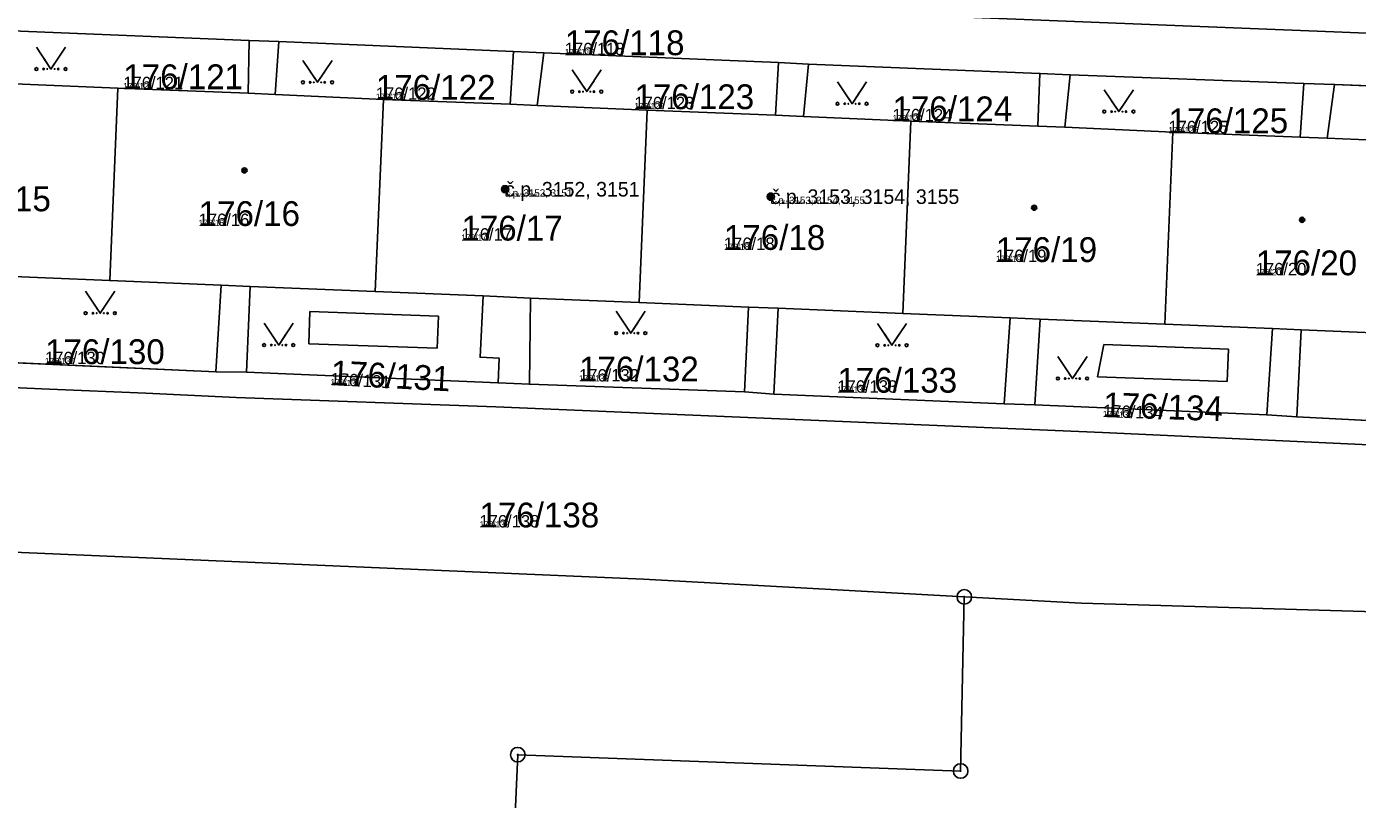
# Model space of a CAD drawing. Extents: x -759873 to -758487, y -975024 to -973516.
# Drawn here: x -759662.7 to -759571.4, y -974909.7 to -974856.7 of the extents above; entities that cross this region are included whole.
import ezdxf

# ---------------------------------------------------------------- set-up
doc = ezdxf.new("R2010")
doc.units = 0
for name, color, linetype in [('KAT_02_hranice parcel', 7, 'Continuous'), ('KAT_03_1000_st čísla parcelní', 7, 'Continuous'), ('KAT_03_1000_čísla parcelní', 7, 'Continuous'), ('KAT_03_1000_čísla popisná', 7, 'Continuous'), ('KAT_03_250_st čísla parcelní', 7, 'Continuous'), ('KAT_03_250_čísla parcelní', 7, 'Continuous'), ('KAT_03_250_čísla popisná', 7, 'Continuous'), ('KAT_03_500_st čísla parcelní', 7, 'Continuous'), ('KAT_03_500_čísla parcelní', 7, 'Continuous'), ('KAT_03_500_čísla popisná', 7, 'Continuous'), ('KAT_04_vnitřní kresba', 7, 'Continuous'), ('KAT_05_1000_značky kultur', 7, 'Continuous'), ('KAT_05_250_značky kultur', 7, 'Continuous'), ('KAT_05_500_značky kultur', 7, 'Continuous'), ('KAT_07_1000_značky budov', 7, 'Continuous'), ('KAT_07_250_značky budov', 7, 'Continuous'), ('KAT_07_500_značky budov', 7, 'Continuous'), ('KAT_11_značky bodu BP', 7, 'Continuous'), ('KAT_14_plocha_budovy', 7, 'Continuous'), ('KAT_14_plocha_pozemek', 7, 'Continuous')]:
    doc.layers.add(name, color=color, linetype=linetype)

msp = doc.modelspace()

# ---------------------------------------------------------------- linework, layer by layer
at = {"layer": 'KAT_02_hranice parcel'}
for p, q in [((-759663.64, -974857.01), (-759647.4, -974857.67)), ((-759645.37, -974857.74), (-759647.4, -974857.67)), ((-759645.37, -974857.74), (-759629.27, -974858.42)), ((-759627.19, -974858.51), (-759629.27, -974858.42)), ((-759627.19, -974858.51), (-759611.09, -974859.18)), ((-759609.03, -974859.28), (-759611.09, -974859.18)), ((-759609.03, -974859.28), (-759593.15, -974859.92)), ((-759591.08, -974860.01), (-759593.15, -974859.92)), ((-759591.08, -974860.01), (-759575.05, -974860.6)), ((-759572.94, -974860.67), (-759575.05, -974860.6)), ((-759656.96, -974874.12), (-759656.41, -974860.94)), ((-759572.94, -974860.67), (-759556.86, -974861.35)), ((-759638.74, -974874.88), (-759638.19, -974861.7)), ((-759620.64, -974875.63), (-759620.1, -974862.45)), ((-759602.55, -974876.37), (-759602.01, -974863.19)), ((-759584.58, -974877.12), (-759584.03, -974863.94)), ((-759665.96, -974879.65), (-759649.68, -974880.37)), ((-759649.68, -974880.37), (-759647.57, -974880.4)), ((-759647.57, -974880.4), (-759630.32, -974881.14)), ((-759630.32, -974881.14), (-759628.17, -974881.23)), ((-759628.17, -974881.23), (-759613.41, -974881.75)), ((-759613.41, -974881.75), (-759611.4, -974881.91)), ((-759611.4, -974881.91), (-759595.61, -974882.57)), ((-759595.61, -974882.57), (-759593.51, -974882.64)), ((-759593.51, -974882.64), (-759577.59, -974883.34)), ((-759577.59, -974883.34), (-759575.54, -974883.47)), ((-759575.54, -974883.47), (-759559.19, -974884.32))]:
    msp.add_line(p, q, dxfattribs=at)
for points in [[(-759558.86, -974857.64), (-759572.99, -974857.06), (-759590.79, -974856.36), (-759612.08, -974855.52)], [(-759656.41, -974860.94), (-759664.04, -974860.6), (-759663.64, -974857.01)], [(-759647.4, -974857.67), (-759647.46, -974861.28), (-759656.41, -974860.94)], [(-759638.19, -974861.7), (-759645.61, -974861.36), (-759645.37, -974857.74)], [(-759629.27, -974858.42), (-759629.5, -974862.03), (-759638.19, -974861.7)], [(-759620.1, -974862.45), (-759627.64, -974862.11), (-759627.19, -974858.51)], [(-759611.09, -974859.18), (-759611.29, -974862.79), (-759620.1, -974862.45)], [(-759602.01, -974863.19), (-759609.38, -974862.87), (-759609.03, -974859.28)], [(-759593.15, -974859.92), (-759593.3, -974863.54), (-759602.01, -974863.19)], [(-759584.03, -974863.94), (-759591.44, -974863.61), (-759591.08, -974860.01)], [(-759575.05, -974860.6), (-759575.29, -974864.28), (-759584.03, -974863.94)], [(-759565.93, -974864.69), (-759573.44, -974864.36), (-759572.94, -974860.67)], [(-759523.06, -974862.69), (-759523.84, -974879.95), (-759532.34, -974886.85), (-759531.93, -974887.1), (-759532.68, -974898.32), (-759561.57, -974897.09), (-759590.3, -974896.25), (-759598.34, -974895.81)], [(-759665.96, -974879.65), (-759665.8, -974873.76), (-759656.96, -974874.12)], [(-759656.96, -974874.12), (-759649.32, -974874.44), (-759649.68, -974880.37)], [(-759647.57, -974880.4), (-759647.32, -974874.52), (-759638.74, -974874.88)], [(-759638.74, -974874.88), (-759631.34, -974875.18), (-759631.56, -974879.38), (-759630.25, -974879.44), (-759630.32, -974881.14)], [(-759628.17, -974881.23), (-759628.1, -974875.32), (-759620.64, -974875.63)], [(-759620.64, -974875.63), (-759613.14, -974875.94), (-759613.41, -974881.75)], [(-759611.4, -974881.91), (-759611.1, -974876.02), (-759602.55, -974876.37)], [(-759602.55, -974876.37), (-759595.19, -974876.68), (-759595.61, -974882.57)], [(-759593.51, -974882.64), (-759593.14, -974876.76), (-759584.58, -974877.12)], [(-759584.58, -974877.12), (-759577.2, -974877.42), (-759577.59, -974883.34)], [(-759575.54, -974883.47), (-759575.23, -974877.51), (-759566.48, -974877.87)], [(-759704.55, -974885.39), (-759692.32, -974885.8), (-759692.32, -974891.5), (-759674.78, -974892.27), (-759648.58, -974893.39), (-759620.34, -974894.6), (-759598.34, -974895.81)], [(-759598.34, -974895.81), (-759598.59, -974907.75), (-759628.97, -974906.63), (-759630.26, -974935.59), (-759598.78, -974936.67), (-759598.41, -974971.14)]]:
    msp.add_lwpolyline(points, dxfattribs=at)
at = {"layer": 'KAT_03_1000_čísla popisná'}
for centre in [(-759629.84, -974867.86), (-759611.62, -974868.37)]:
    msp.add_circle(centre, 0.25, dxfattribs=at)
at = {"layer": 'KAT_03_250_čísla popisná'}
for centre in [(-759629.84, -974867.86), (-759611.62, -974868.37)]:
    msp.add_circle(centre, 0.0625, dxfattribs=at)
at = {"layer": 'KAT_03_500_čísla popisná'}
for centre in [(-759629.84, -974867.86), (-759611.62, -974868.37)]:
    msp.add_circle(centre, 0.125, dxfattribs=at)
at = {"layer": 'KAT_04_vnitřní kresba'}
for p, q in [((-759647.46, -974861.28), (-759645.61, -974861.36)), ((-759629.5, -974862.03), (-759627.64, -974862.11)), ((-759611.29, -974862.79), (-759609.38, -974862.87)), ((-759593.3, -974863.54), (-759591.44, -974863.61)), ((-759575.29, -974864.28), (-759573.44, -974864.36)), ((-759649.32, -974874.44), (-759647.32, -974874.52)), ((-759631.34, -974875.18), (-759628.1, -974875.32)), ((-759613.14, -974875.94), (-759611.1, -974876.02)), ((-759643.29, -974878.46), (-759643.23, -974876.24)), ((-759643.23, -974876.24), (-759634.41, -974876.56)), ((-759634.49, -974878.76), (-759634.41, -974876.56)), ((-759595.19, -974876.68), (-759593.14, -974876.76)), ((-759577.2, -974877.42), (-759575.23, -974877.51)), ((-759643.29, -974878.46), (-759634.49, -974878.76)), ((-759589.21, -974880.73), (-759588.77, -974878.51)), ((-759588.77, -974878.51), (-759580.22, -974878.83)), ((-759580.31, -974881.04), (-759580.22, -974878.83)), ((-759670.56, -974881.16), (-759661.09, -974881.56)), ((-759661.09, -974881.56), (-759654.48, -974881.84)), ((-759589.21, -974880.73), (-759580.31, -974881.04)), ((-759654.48, -974881.84), (-759648.28, -974882.15)), ((-759648.28, -974882.15), (-759630.47, -974882.79)), ((-759630.47, -974882.79), (-759588.86, -974884.55)), ((-759588.86, -974884.55), (-759570.57, -974885.39))]:
    msp.add_line(p, q, dxfattribs=at)
at = {"layer": 'KAT_05_1000_značky kultur'}
for points in [[(-759661.99, -974858.119), (-759660.99, -974859.62), (-759659.99, -974858.119)], [(-759643.71, -974859.029), (-759642.71, -974860.53), (-759641.71, -974859.029)], [(-759625.24, -974859.669), (-759624.24, -974861.17), (-759623.24, -974859.669)], [(-759607.04, -974860.499), (-759606.04, -974862), (-759605.04, -974860.499)], [(-759588.74, -974861.039), (-759587.74, -974862.54), (-759586.74, -974861.039)], [(-759658.61, -974874.859), (-759657.61, -974876.36), (-759656.61, -974874.859)], [(-759622.22, -974876.229), (-759621.22, -974877.73), (-759620.22, -974876.229)], [(-759646.37, -974877.049), (-759645.37, -974878.55), (-759644.37, -974877.049)], [(-759604.3, -974877.059), (-759603.3, -974878.56), (-759602.3, -974877.059)], [(-759591.92, -974879.339), (-759590.92, -974880.84), (-759589.92, -974879.339)]]:
    msp.add_lwpolyline(points, dxfattribs=at)
for centre in [(-759661.99, -974859.619), (-759659.99, -974859.619), (-759643.71, -974860.529), (-759641.71, -974860.529), (-759625.24, -974861.169), (-759623.24, -974861.169), (-759607.04, -974861.999), (-759605.04, -974861.999), (-759588.74, -974862.539), (-759586.74, -974862.539), (-759658.61, -974876.359), (-759656.61, -974876.359), (-759622.22, -974877.729), (-759620.22, -974877.729), (-759646.37, -974878.549), (-759644.37, -974878.549), (-759604.3, -974878.559), (-759602.3, -974878.559), (-759591.92, -974880.839), (-759589.92, -974880.839)]:
    msp.add_circle(centre, 0.1, dxfattribs=at)
at = {"layer": 'KAT_05_250_značky kultur'}
for points in [[(-759661.24, -974859.245), (-759660.99, -974859.62), (-759660.74, -974859.245)], [(-759642.96, -974860.155), (-759642.71, -974860.53), (-759642.46, -974860.155)], [(-759624.49, -974860.795), (-759624.24, -974861.17), (-759623.99, -974860.795)], [(-759606.29, -974861.625), (-759606.04, -974862), (-759605.79, -974861.625)], [(-759587.99, -974862.165), (-759587.74, -974862.54), (-759587.49, -974862.165)], [(-759657.86, -974875.985), (-759657.61, -974876.36), (-759657.36, -974875.985)], [(-759621.47, -974877.355), (-759621.22, -974877.73), (-759620.97, -974877.355)], [(-759645.62, -974878.175), (-759645.37, -974878.55), (-759645.12, -974878.175)], [(-759603.55, -974878.185), (-759603.3, -974878.56), (-759603.05, -974878.185)], [(-759591.17, -974880.465), (-759590.92, -974880.84), (-759590.67, -974880.465)]]:
    msp.add_lwpolyline(points, dxfattribs=at)
for centre in [(-759661.24, -974859.62), (-759660.74, -974859.62), (-759642.96, -974860.53), (-759642.46, -974860.53), (-759624.49, -974861.17), (-759623.99, -974861.17), (-759606.29, -974862), (-759605.79, -974862), (-759587.99, -974862.54), (-759587.49, -974862.54), (-759657.86, -974876.36), (-759657.36, -974876.36), (-759621.47, -974877.73), (-759620.97, -974877.73), (-759645.62, -974878.55), (-759645.12, -974878.55), (-759603.55, -974878.56), (-759603.05, -974878.56), (-759591.17, -974880.84), (-759590.67, -974880.84)]:
    msp.add_circle(centre, 0.025, dxfattribs=at)
at = {"layer": 'KAT_05_500_značky kultur'}
for points in [[(-759661.49, -974858.87), (-759660.99, -974859.62), (-759660.49, -974858.87)], [(-759643.21, -974859.78), (-759642.71, -974860.53), (-759642.21, -974859.78)], [(-759624.74, -974860.42), (-759624.24, -974861.17), (-759623.74, -974860.42)], [(-759606.54, -974861.25), (-759606.04, -974862), (-759605.54, -974861.25)], [(-759588.24, -974861.79), (-759587.74, -974862.54), (-759587.24, -974861.79)], [(-759658.11, -974875.61), (-759657.61, -974876.36), (-759657.11, -974875.61)], [(-759621.72, -974876.98), (-759621.22, -974877.73), (-759620.72, -974876.98)], [(-759645.87, -974877.799), (-759645.37, -974878.55), (-759644.87, -974877.799)], [(-759603.8, -974877.809), (-759603.3, -974878.56), (-759602.8, -974877.809)], [(-759591.42, -974880.09), (-759590.92, -974880.84), (-759590.42, -974880.09)]]:
    msp.add_lwpolyline(points, dxfattribs=at)
for centre in [(-759661.49, -974859.62), (-759660.49, -974859.62), (-759643.21, -974860.53), (-759642.21, -974860.53), (-759624.74, -974861.17), (-759623.74, -974861.17), (-759606.54, -974862), (-759605.54, -974862), (-759588.24, -974862.54), (-759587.24, -974862.54), (-759658.11, -974876.36), (-759657.11, -974876.36), (-759621.72, -974877.73), (-759620.72, -974877.73), (-759645.87, -974878.55), (-759644.87, -974878.55), (-759603.8, -974878.56), (-759602.8, -974878.56), (-759591.42, -974880.84), (-759590.42, -974880.84)]:
    msp.add_circle(centre, 0.05, dxfattribs=at)
at = {"layer": 'KAT_07_1000_značky budov'}
for centre in [(-759647.717, -974866.569), (-759629.847, -974867.859), (-759611.627, -974868.369), (-759593.547, -974869.129), (-759575.167, -974869.959)]:
    msp.add_circle(centre, 0.175, dxfattribs=at)
at = {"layer": 'KAT_07_250_značky budov'}
for centre in [(-759647.712, -974866.57), (-759629.842, -974867.86), (-759611.622, -974868.37), (-759593.542, -974869.13), (-759575.162, -974869.96)]:
    msp.add_circle(centre, 0.0437, dxfattribs=at)
at = {"layer": 'KAT_07_500_značky budov'}
for centre in [(-759647.713, -974866.57), (-759629.843, -974867.86), (-759611.623, -974868.37), (-759593.543, -974869.13), (-759575.163, -974869.96)]:
    msp.add_circle(centre, 0.0875, dxfattribs=at)
at = {"layer": 'KAT_11_značky bodu BP'}
for centre, radius in [((-759598.34, -974895.81), 0.5), ((-759598.34, -974895.81), 0.0303), ((-759628.97, -974906.63), 0.5), ((-759628.97, -974906.63), 0.0303), ((-759598.59, -974907.75), 0.5), ((-759598.59, -974907.75), 0.0303)]:
    msp.add_circle(centre, radius, dxfattribs=at)
at = {"layer": 'KAT_14_plocha_budovy'}
for points in [[(-759678.4, -974860), (-759680.2, -974859.92), (-759689.02, -974859.59), (-759692.8, -974859.4), (-759694.64, -974859.32), (-759703.66, -974858.95), (-759704.17, -974872.17), (-759696.82, -974872.47), (-759685.97, -974872.92), (-759678.93, -974873.21), (-759671.59, -974873.52), (-759667.8, -974873.67), (-759665.8, -974873.76), (-759656.96, -974874.12), (-759656.41, -974860.94), (-759664.04, -974860.6), (-759665.9, -974860.52), (-759674.64, -974860.19)], [(-759647.32, -974874.52), (-759638.74, -974874.88), (-759631.34, -974875.18), (-759628.1, -974875.32), (-759620.64, -974875.63), (-759620.1, -974862.45), (-759627.64, -974862.11), (-759629.5, -974862.03), (-759638.19, -974861.7), (-759645.61, -974861.36), (-759647.46, -974861.28), (-759656.41, -974860.94), (-759656.96, -974874.12), (-759649.32, -974874.44)], [(-759566.48, -974877.87), (-759565.93, -974864.69), (-759573.44, -974864.36), (-759575.29, -974864.28), (-759584.03, -974863.94), (-759591.44, -974863.61), (-759593.3, -974863.54), (-759602.01, -974863.19), (-759609.38, -974862.87), (-759611.29, -974862.79), (-759620.1, -974862.45), (-759620.64, -974875.63), (-759613.14, -974875.94), (-759611.1, -974876.02), (-759602.55, -974876.37), (-759595.19, -974876.68), (-759593.14, -974876.76), (-759584.58, -974877.12), (-759577.2, -974877.42), (-759575.23, -974877.51)]]:
    msp.add_lwpolyline(points, close=True, dxfattribs=at)
at = {"layer": 'KAT_14_plocha_pozemek'}
for points in [[(-759557.33, -974802.75), (-759572.9, -974800.89), (-759576.85, -974804.99), (-759579.53, -974810.64), (-759579.88, -974820.55), (-759583.32, -974820.34), (-759583.29, -974819.43), (-759588.48, -974819.39), (-759588.94, -974831.66), (-759590.75, -974831.6), (-759591.01, -974838.82), (-759603.4, -974838.36), (-759602.69, -974819.15), (-759606.69, -974818.97), (-759608.06, -974821.13), (-759608.23, -974826.18), (-759608.5, -974830.39), (-759612.04, -974837.62), (-759612.06, -974840.11), (-759612.01, -974853.96), (-759612.08, -974855.52), (-759590.79, -974856.36), (-759572.99, -974857.06), (-759558.86, -974857.64)], [(-759558.86, -974857.64), (-759572.99, -974857.06), (-759590.79, -974856.36), (-759612.08, -974855.52), (-759613.51, -974855.38), (-759629.09, -974854.78), (-759656.08, -974853.68), (-759679.76, -974852.8)], [(-759445.5, -974855.85), (-759459.93, -974855.14), (-759460.02, -974857.37), (-759508.63, -974855.12), (-759522.81, -974859.11), (-759523.06, -974862.69), (-759523.84, -974879.95), (-759532.34, -974886.85), (-759531.93, -974887.1), (-759532.68, -974898.32), (-759561.57, -974897.09), (-759590.3, -974896.25), (-759598.34, -974895.81), (-759598.59, -974907.75), (-759628.97, -974906.63), (-759630.26, -974935.59)], [(-759663.64, -974857.01), (-759647.4, -974857.67), (-759645.37, -974857.74), (-759629.27, -974858.42), (-759627.19, -974858.51), (-759611.09, -974859.18), (-759609.03, -974859.28), (-759593.15, -974859.92), (-759591.08, -974860.01), (-759575.05, -974860.6), (-759572.94, -974860.67), (-759556.86, -974861.35)], [(-759559.19, -974884.32), (-759575.54, -974883.47), (-759577.59, -974883.34), (-759593.51, -974882.64), (-759595.61, -974882.57), (-759611.4, -974881.91), (-759613.41, -974881.75), (-759628.17, -974881.23), (-759630.32, -974881.14), (-759647.57, -974880.4), (-759649.68, -974880.37), (-759665.96, -974879.65)], [(-759663.8, -974967.02), (-759644.32, -974968.81), (-759624.01, -974970.63), (-759604.4, -974972.46), (-759601.29, -974972.38), (-759599.61, -974971.7), (-759598.41, -974971.14), (-759598.78, -974936.67), (-759630.26, -974935.59), (-759628.97, -974906.63), (-759598.59, -974907.75), (-759598.34, -974895.81), (-759620.34, -974894.6), (-759648.58, -974893.39), (-759674.78, -974892.27)], [(-759674.78, -974892.27), (-759648.58, -974893.39), (-759620.34, -974894.6), (-759598.34, -974895.81), (-759590.3, -974896.25), (-759561.57, -974897.09)]]:
    msp.add_lwpolyline(points, dxfattribs=at)
for points in [[(-759656.41, -974860.94), (-759664.04, -974860.6), (-759663.64, -974857.01), (-759665.73, -974856.93), (-759665.9, -974860.52), (-759674.64, -974860.19), (-759674.91, -974866.78), (-759671.31, -974866.93), (-759671.59, -974873.52), (-759667.8, -974873.67), (-759668.11, -974874.8), (-759668.14, -974879.63), (-759665.96, -974879.65), (-759665.8, -974873.76), (-759656.96, -974874.12)], [(-759663.64, -974857.01), (-759664.04, -974860.6), (-759656.41, -974860.94), (-759647.46, -974861.28), (-759647.4, -974857.67)], [(-759649.32, -974874.44), (-759649.68, -974880.37), (-759647.57, -974880.4), (-759647.32, -974874.52), (-759638.74, -974874.88), (-759638.19, -974861.7), (-759645.61, -974861.36), (-759645.37, -974857.74), (-759647.4, -974857.67), (-759647.46, -974861.28), (-759656.41, -974860.94), (-759656.96, -974874.12)], [(-759645.37, -974857.74), (-759645.61, -974861.36), (-759638.19, -974861.7), (-759629.5, -974862.03), (-759629.27, -974858.42)], [(-759620.64, -974875.63), (-759620.1, -974862.45), (-759627.64, -974862.11), (-759627.19, -974858.51), (-759629.27, -974858.42), (-759629.5, -974862.03), (-759638.19, -974861.7), (-759638.74, -974874.88), (-759631.34, -974875.18), (-759631.56, -974879.38), (-759630.25, -974879.44), (-759630.32, -974881.14), (-759628.17, -974881.23), (-759628.1, -974875.32)], [(-759627.19, -974858.51), (-759627.64, -974862.11), (-759620.1, -974862.45), (-759611.29, -974862.79), (-759611.09, -974859.18)], [(-759613.14, -974875.94), (-759613.41, -974881.75), (-759611.4, -974881.91), (-759611.1, -974876.02), (-759602.55, -974876.37), (-759602.01, -974863.19), (-759609.38, -974862.87), (-759609.03, -974859.28), (-759611.09, -974859.18), (-759611.29, -974862.79), (-759620.1, -974862.45), (-759620.64, -974875.63)], [(-759609.03, -974859.28), (-759609.38, -974862.87), (-759602.01, -974863.19), (-759593.3, -974863.54), (-759593.15, -974859.92)], [(-759584.03, -974863.94), (-759591.44, -974863.61), (-759591.08, -974860.01), (-759593.15, -974859.92), (-759593.3, -974863.54), (-759602.01, -974863.19), (-759602.55, -974876.37), (-759595.19, -974876.68), (-759595.61, -974882.57), (-759593.51, -974882.64), (-759593.14, -974876.76), (-759584.58, -974877.12)], [(-759591.08, -974860.01), (-759591.44, -974863.61), (-759584.03, -974863.94), (-759575.29, -974864.28), (-759575.05, -974860.6)], [(-759566.48, -974877.87), (-759565.93, -974864.69), (-759573.44, -974864.36), (-759572.94, -974860.67), (-759575.05, -974860.6), (-759575.29, -974864.28), (-759584.03, -974863.94), (-759584.58, -974877.12), (-759577.2, -974877.42), (-759577.59, -974883.34), (-759575.54, -974883.47), (-759575.23, -974877.51)], [(-759572.94, -974860.67), (-759573.44, -974864.36), (-759565.93, -974864.69), (-759557.08, -974865.04), (-759556.86, -974861.35)], [(-759649.68, -974880.37), (-759649.32, -974874.44), (-759656.96, -974874.12), (-759665.8, -974873.76), (-759665.96, -974879.65)], [(-759630.32, -974881.14), (-759630.25, -974879.44), (-759631.56, -974879.38), (-759631.34, -974875.18), (-759638.74, -974874.88), (-759647.32, -974874.52), (-759647.57, -974880.4)], [(-759613.41, -974881.75), (-759613.14, -974875.94), (-759620.64, -974875.63), (-759628.1, -974875.32), (-759628.17, -974881.23)], [(-759595.61, -974882.57), (-759595.19, -974876.68), (-759602.55, -974876.37), (-759611.1, -974876.02), (-759611.4, -974881.91)], [(-759577.59, -974883.34), (-759577.2, -974877.42), (-759584.58, -974877.12), (-759593.14, -974876.76), (-759593.51, -974882.64)], [(-759559.19, -974884.32), (-759558.99, -974878.18), (-759566.48, -974877.87), (-759575.23, -974877.51), (-759575.54, -974883.47)]]:
    msp.add_lwpolyline(points, close=True, dxfattribs=at)

# ---------------------------------------------------------------- texts
at = {"layer": 'KAT_03_1000_st čísla parcelní'}
for s, p in [('176/15', (-759667.95, -974869.37)), ('176/16', (-759650.86, -974870.38)), ('176/17', (-759632.84, -974871.38)), ('176/18', (-759614.83, -974872.02)), ('176/19', (-759596.18, -974872.85)), ('176/20', (-759578.35, -974873.76))]:
    msp.add_text(s, height=1.7, dxfattribs=at).set_placement(p)
at = {"layer": 'KAT_03_1000_čísla parcelní'}
for s, p in [('176/118', (-759625.75, -974858.669)), ('176/121', (-759656.03, -974861)), ('176/122', (-759638.71, -974861.73)), ('176/123', (-759620.97, -974862.37)), ('176/124', (-759603.27, -974863.2)), ('176/125', (-759584.34, -974864.02)), ('176/130', (-759661.4, -974879.85)), ('176/132', (-759624.77, -974881.039)), ('176/133', (-759607.05, -974881.809)), ('176/138', (-759631.6, -974891.049))]:
    msp.add_text(s, height=1.7, dxfattribs=at).set_placement(p)
for s, rotation, p in [('176/131', 357, (-759641.834, -974881.288)), ('176/134', 358, (-759588.839, -974883.479))]:
    msp.add_text(s, height=1.7, rotation=rotation, dxfattribs=at).set_placement(p)
at = {"layer": 'KAT_03_1000_čísla popisná'}
for s, p in [('č.p. 3152, 3151', (-759629.84, -974868.36)), ('č.p. 3153, 3154, 3155', (-759611.62, -974868.87))]:
    msp.add_text(s, height=1, dxfattribs=at).set_placement(p)
at = {"layer": 'KAT_03_250_st čísla parcelní'}
for s, p in [('176/16', (-759650.86, -974870.38)), ('176/17', (-759632.84, -974871.38)), ('176/18', (-759614.83, -974872.02)), ('176/19', (-759596.18, -974872.85)), ('176/20', (-759578.35, -974873.76))]:
    msp.add_text(s, height=0.425, dxfattribs=at).set_placement(p)
at = {"layer": 'KAT_03_250_čísla parcelní'}
for s, p in [('176/118', (-759625.75, -974858.669)), ('176/121', (-759656.03, -974861)), ('176/122', (-759638.71, -974861.73)), ('176/123', (-759620.97, -974862.37)), ('176/124', (-759603.27, -974863.2)), ('176/125', (-759584.34, -974864.02)), ('176/130', (-759661.4, -974879.85)), ('176/132', (-759624.77, -974881.039)), ('176/133', (-759607.05, -974881.809)), ('176/138', (-759631.6, -974891.049))]:
    msp.add_text(s, height=0.425, dxfattribs=at).set_placement(p)
for s, rotation, p in [('176/131', 357, (-759641.834, -974881.288)), ('176/134', 358, (-759588.839, -974883.479))]:
    msp.add_text(s, height=0.425, rotation=rotation, dxfattribs=at).set_placement(p)
at = {"layer": 'KAT_03_250_čísla popisná'}
for s, p in [('č.p. 3152, 3151', (-759629.84, -974868.36)), ('č.p. 3153, 3154, 3155', (-759611.62, -974868.87))]:
    msp.add_text(s, height=0.25, dxfattribs=at).set_placement(p)
at = {"layer": 'KAT_03_500_st čísla parcelní'}
for s, p in [('176/16', (-759650.86, -974870.38)), ('176/17', (-759632.84, -974871.38)), ('176/18', (-759614.83, -974872.02)), ('176/19', (-759596.18, -974872.85)), ('176/20', (-759578.35, -974873.76))]:
    msp.add_text(s, height=0.85, dxfattribs=at).set_placement(p)
at = {"layer": 'KAT_03_500_čísla parcelní'}
for s, p in [('176/118', (-759625.75, -974858.669)), ('176/121', (-759656.03, -974861)), ('176/122', (-759638.71, -974861.73)), ('176/123', (-759620.97, -974862.37)), ('176/124', (-759603.27, -974863.2)), ('176/125', (-759584.34, -974864.02)), ('176/130', (-759661.4, -974879.85)), ('176/132', (-759624.77, -974881.039)), ('176/133', (-759607.05, -974881.809)), ('176/138', (-759631.6, -974891.049))]:
    msp.add_text(s, height=0.85, dxfattribs=at).set_placement(p)
for s, rotation, p in [('176/131', 357, (-759641.834, -974881.288)), ('176/134', 358, (-759588.839, -974883.479))]:
    msp.add_text(s, height=0.85, rotation=rotation, dxfattribs=at).set_placement(p)
at = {"layer": 'KAT_03_500_čísla popisná'}
for s, p in [('č.p. 3152, 3151', (-759629.84, -974868.36)), ('č.p. 3153, 3154, 3155', (-759611.62, -974868.87))]:
    msp.add_text(s, height=0.5, dxfattribs=at).set_placement(p)

doc.saveas('drawing.dxf')
